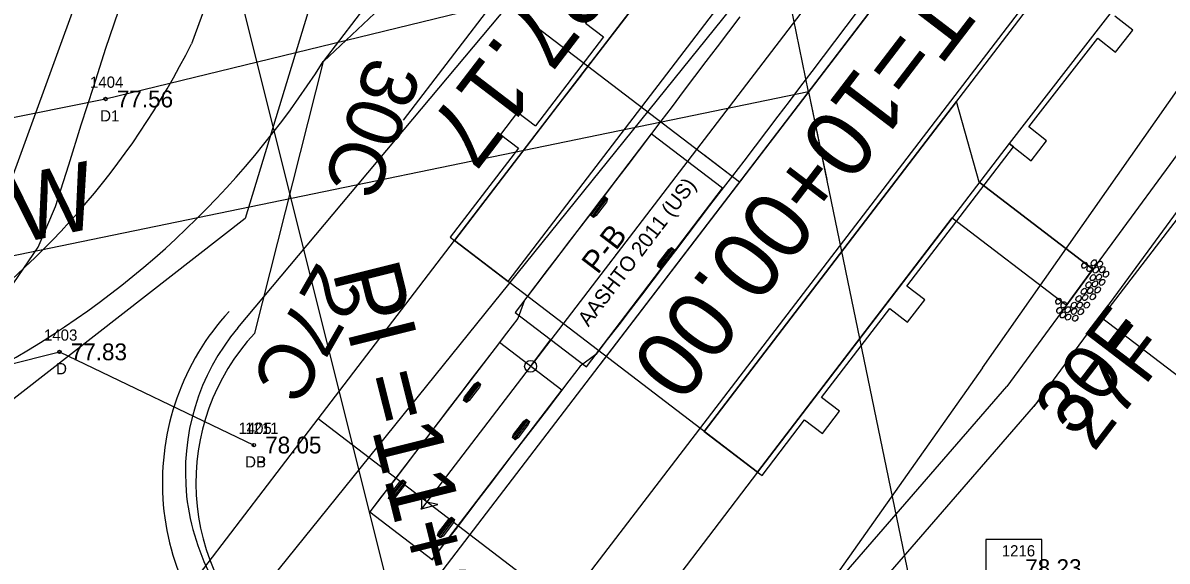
# Model space of a CAD drawing. Extents: x 2500794 to 2511032, y 910653 to 917533.
# Drawn here: x 2506102.2 to 2506204.2, y 913947.8 to 913995.8 of the extents above; entities that cross this region are included whole.
import ezdxf

# ---------------------------------------------------------------- set-up
doc = ezdxf.new("R2010")
doc.units = 0
for name, color, linetype in [('RD_EX_Driveway', 7, 'Continuous'), ('RD_EX_Driveway_txCode', 7, 'Continuous'), ('RD_EX_Road', 7, 'Continuous'), ('RD_EX_RW', 7, 'Continuous'), ('RD_EX_TX_Driveway_ELEV', 7, 'Continuous'), ('RD_EX_UT', 7, 'Continuous'), ('RD_EX_UT_txCode', 7, 'Continuous'), ('RD_HC_Cl', 7, 'Continuous'), ('RD_HC_Data', 7, 'Continuous'), ('RD_HC_Data_Rel', 7, 'Continuous'), ('RD_HC_Data_Tic', 7, 'Continuous'), ('RD_HC_Survey_ELEV', 7, 'Continuous'), ('RD_PD_ALT1_TnTmp', 7, 'Continuous'), ('RD_PD_ALT1_TrvlWay', 7, 'Continuous'), ('RD_PD_ALT2_TrvlWay', 7, 'Continuous'), ('RD_PD_Bridge', 7, 'Continuous'), ('RD_PD_CstnLmt', 7, 'Continuous'), ('RD_PD_CstnLmt_TX', 7, 'Continuous'), ('RD_PD_Detour', 7, 'Continuous'), ('RD_PD_GR', 7, 'Continuous'), ('RD_PD_PaintMed', 7, 'Continuous'), ('RD_PD_PaveShd', 7, 'Continuous'), ('RD_PD_Signals', 7, 'Continuous'), ('RD_Sketch10', 7, 'Continuous'), ('RD_SMD_Locator', 7, 'Continuous'), ('RD_XS_NPDES', 7, 'Continuous')]:
    doc.layers.add(name, color=color, linetype=linetype)

msp = doc.modelspace()

# ---------------------------------------------------------------- linework, layer by layer
at = {"layer": 'RD_EX_Driveway'}
for points in [[(2505985.77, 913963.59), (2506043.74, 913975.78), (2506109.6, 913989.05), (2506154.74, 914000.1)], [(2505819.54, 913956.76), (2505827.1, 913947.15), (2505840.35, 913935.26), (2505856.8, 913926.65), (2505912.43, 913930.56), (2505969.91, 913935.82), (2505992.8, 913939.07), (2506008.73, 913942.16), (2506105.49, 913966.5), (2506122.82, 913958.19)]]:
    msp.add_lwpolyline(points, dxfattribs=at)
at = {"layer": 'RD_EX_Road'}
for points in [[(2506114.01, 913933.8), (2506123.61, 913945.35), (2506183.7, 914019.9), (2506246.75, 914102.24), (2506309.52, 914184.62), (2506366.78, 914260.38), (2506431.55, 914345.25), (2506455.95, 914376.74), (2506469.75, 914395.23), (2506492.7, 914425.08), (2506555.84, 914508.26), (2506617.75, 914589.02), (2506679.77, 914670.81), (2506740.35, 914750.22)], [(2506132.31, 913920.14), (2506200.99, 914009.83), (2506228.78, 914046.14), (2506238.19, 914058.36), (2506261.83, 914089.97), (2506324.5, 914172.22), (2506382.84, 914247.97), (2506424.88, 914303.73), (2506446.4, 914331.89), (2506508.34, 914413.09), (2506571.21, 914495.53), (2506633.01, 914576.81), (2506694.83, 914657.95), (2506756.78, 914739.18)]]:
    msp.add_lwpolyline(points, dxfattribs=at)
at = {"layer": 'RD_EX_RW'}
for p, q in [((2506198.38, 913969.53), (2506826.41, 914790.99)), ((2506231.75, 913944.02), (2506198.38, 913969.53))]:
    msp.add_line(p, q, dxfattribs=at)
at = {"layer": 'RD_EX_UT'}
for p, q in [((2506193.06, 913949.76), (2506188.06, 913949.76)), ((2506188.06, 913949.76), (2506188.06, 913944.76)), ((2506193.06, 913944.76), (2506193.06, 913949.76))]:
    msp.add_line(p, q, dxfattribs=at)
at = {"layer": 'RD_HC_Cl'}
for p, q in [((2505807.57, 913512.69), (2506748.89, 914743.92)), ((2506172.26, 913989.7), (2505988.17, 913951.65))]:
    msp.add_line(p, q, dxfattribs=at)
at = {"layer": 'RD_HC_Data'}
for p, q in [((2506112.07, 914036.23), (2506140.23, 913923.75)), ((2506172.26, 913989.7), (2506196.98, 913870.15))]:
    msp.add_line(p, q, dxfattribs=at)
at = {"layer": 'RD_HC_Data_Rel'}
for p, q in [((2506234.44, 914115.77), (2506136.12, 913987.17)), ((2506256.03, 914099.26), (2506153.68, 913965.39))]:
    msp.add_line(p, q, dxfattribs=at)
at = {"layer": 'RD_HC_Data_Tic'}
for p, q in [((2506172.26, 913989.7), (2506170.64, 913997.54)), ((2506172.26, 913989.7), (2506173.88, 913981.87)), ((2506166.09, 913981.63), (2506162.91, 913984.06)), ((2506166.09, 913981.63), (2506162.91, 913984.06))]:
    msp.add_line(p, q, dxfattribs=at)
at = {"layer": 'RD_PD_ALT1_TnTmp'}
for p, q in [((2506206.92, 914042.96), (2506137.76, 913952.5)), ((2506100.56, 913980.07), (2506123.05, 914041.87)), ((2506158.23, 913985.93), (2506146.11, 913970.02)), ((2506164.59, 913981.09), (2506158.23, 913985.93)), ((2506152.48, 913965.17), (2506164.59, 913981.09)), ((2506152.85, 913978.66), (2506154.12, 913980.32)), ((2506152.96, 913978.58), (2506154.22, 913980.24)), ((2506153.06, 913978.5), (2506154.32, 913980.16)), ((2506158.81, 913974.13), (2506160.07, 913975.79)), ((2506158.91, 913974.05), (2506160.17, 913975.71)), ((2506159.01, 913973.97), (2506160.27, 913975.63)), ((2506146.11, 913970.02), (2506152.48, 913965.17)), ((2506144.7, 913967.34), (2506133.16, 913952.24)), ((2506150.26, 913963.08), (2506144.7, 913967.34)), ((2506147.48, 913965.21), (2506149.3, 913967.6)), ((2506152.48, 913965.17), (2506152.48, 913965.17)), ((2506141.53, 913962.15), (2506142.79, 913963.81)), ((2506141.63, 913962.07), (2506142.9, 913963.73)), ((2506141.74, 913962), (2506143, 913963.65)), ((2506138.72, 913947.99), (2506150.26, 913963.08)), ((2506145.88, 913958.83), (2506147.15, 913960.48)), ((2506145.98, 913958.75), (2506147.25, 913960.4)), ((2506146.09, 913958.67), (2506147.35, 913960.32)), ((2506134.85, 913953.42), (2506136.11, 913955.07)), ((2506134.95, 913953.34), (2506136.22, 913954.99)), ((2506135.05, 913953.26), (2506136.32, 913954.91)), ((2506133.16, 913952.24), (2506138.72, 913947.99)), ((2506139.2, 913950.09), (2506140.47, 913951.74)), ((2506139.3, 913950.01), (2506140.57, 913951.66)), ((2506139.41, 913949.93), (2506140.67, 913951.58)), ((2506138.72, 913947.99), (2506138.72, 913947.99))]:
    msp.add_line(p, q, dxfattribs=at)
for points in [[(2506101.43, 913972.67), (2506103.58, 913975.85), (2506105.13, 913979.46), (2506106.31, 913983.17), (2506107.43, 913986.74), (2506108.54, 913990.19), (2506109.63, 913993.57), (2506110.74, 913996.88)], [(2506166.12, 913996.37), (2506165.12, 913995.04), (2506164.11, 913993.71), (2506163.11, 913992.38), (2506162.1, 913991.05), (2506161.09, 913989.72), (2506160.09, 913988.39), (2506159.08, 913987.06), (2506158.07, 913985.73), (2506157.06, 913984.4), (2506156.05, 913983.07), (2506155.04, 913981.74), (2506154.03, 913980.42), (2506153.02, 913979.09), (2506152.01, 913977.76), (2506150.99, 913976.43), (2506149.98, 913975.1), (2506148.97, 913973.78), (2506147.96, 913972.45), (2506146.95, 913971.12), (2506146.34, 913969.48), (2506145.33, 913968.16), (2506144.31, 913966.83), (2506143.3, 913965.51), (2506142.28, 913964.18), (2506141.27, 913962.85), (2506140.26, 913961.53), (2506139.24, 913960.2), (2506138.23, 913958.87), (2506137.21, 913957.55), (2506136.2, 913956.22), (2506135.19, 913954.89), (2506134.17, 913953.57), (2506133.16, 913952.24)], [(2506176.58, 913996.84), (2506175.57, 913995.51), (2506174.56, 913994.17), (2506173.55, 913992.84), (2506172.54, 913991.51), (2506171.53, 913990.18), (2506170.52, 913988.84), (2506169.51, 913987.51), (2506168.5, 913986.18), (2506167.49, 913984.85), (2506166.48, 913983.52), (2506165.47, 913982.19), (2506164.45, 913980.87), (2506163.44, 913979.54), (2506162.43, 913978.21), (2506161.42, 913976.88), (2506160.4, 913975.55), (2506159.39, 913974.23), (2506158.38, 913972.9), (2506157.36, 913971.57), (2506156.35, 913970.24), (2506155.34, 913968.92), (2506154.32, 913967.59), (2506153.31, 913966.26), (2506151.9, 913965.23), (2506150.89, 913963.91), (2506149.87, 913962.58), (2506148.86, 913961.25), (2506147.85, 913959.93), (2506146.83, 913958.6), (2506145.82, 913957.28), (2506144.8, 913955.95), (2506143.79, 913954.62), (2506142.77, 913953.3), (2506141.76, 913951.97), (2506140.75, 913950.64), (2506139.73, 913949.32), (2506138.72, 913947.99)]]:
    msp.add_lwpolyline(points, dxfattribs=at)
for points in [[(2506153.09, 913978.48), (2506152.83, 913978.68), (2506152.93, 913978.97), (2506153.84, 913980.16), (2506154.09, 913980.34), (2506154.35, 913980.14), (2506154.25, 913979.85), (2506153.34, 913978.66)], [(2506159.04, 913973.95), (2506158.78, 913974.15), (2506158.88, 913974.44), (2506159.79, 913975.63), (2506160.04, 913975.81), (2506160.3, 913975.61), (2506160.2, 913975.32), (2506159.29, 913974.12)], [(2506141.76, 913961.98), (2506141.5, 913962.17), (2506141.6, 913962.46), (2506142.51, 913963.66), (2506142.77, 913963.83), (2506143.03, 913963.63), (2506142.93, 913963.34), (2506142.02, 913962.15)], [(2506146.11, 913958.65), (2506145.86, 913958.85), (2506145.95, 913959.14), (2506146.87, 913960.33), (2506147.12, 913960.5), (2506147.38, 913960.3), (2506147.28, 913960.01), (2506146.37, 913958.82)], [(2506135.08, 913953.24), (2506134.82, 913953.43), (2506134.92, 913953.73), (2506135.83, 913954.92), (2506136.09, 913955.09), (2506136.35, 913954.89), (2506136.25, 913954.6), (2506135.33, 913953.41)], [(2506137.76, 913952.5), (2506139.21, 913952.89), (2506138.22, 913953.1), (2506137.76, 913954)], [(2506139.43, 913949.91), (2506139.17, 913950.11), (2506139.27, 913950.4), (2506140.18, 913951.59), (2506140.44, 913951.76), (2506140.7, 913951.56), (2506140.6, 913951.27), (2506139.69, 913950.08)]]:
    msp.add_lwpolyline(points, close=True, dxfattribs=at)
for centre, radius in [((2506147.48, 913965.21), 0.533), ((2506137.76, 913952.5), 0.0417), ((2506133.16, 913952.24), 0.0417), ((2506138.72, 913947.99), 0.0417)]:
    msp.add_circle(centre, radius, dxfattribs=at)
at = {"layer": 'RD_PD_ALT1_TrvlWay'}
for p, q in [((2506162.95, 913959.41), (2506387.41, 914253)), ((2506145.47, 913972.77), (2506215.72, 914064.66))]:
    msp.add_line(p, q, dxfattribs=at)
at = {"layer": 'RD_PD_ALT2_TrvlWay'}
msp.add_line((2506148.92, 914080.9), (2506117.26, 913993.98), dxfattribs=at)
msp.add_arc((2506053.87, 914025.71), 70.89, 275.1042, 333.4112, dxfattribs=at)
at = {"layer": 'RD_PD_Bridge'}
for p, q in [((2506140.71, 913976.42), (2506152.85, 913992.31)), ((2506128.56, 913960.53), (2506140.71, 913976.42)), ((2506167.72, 913955.77), (2506140.71, 913976.42)), ((2506007.09, 913801.65), (2506128.56, 913960.53)), ((2506155.57, 913939.88), (2506128.56, 913960.53)), ((2506167.72, 913955.77), (2506155.57, 913939.88))]:
    msp.add_line(p, q, dxfattribs=at)
at = {"layer": 'RD_PD_CstnLmt'}
for p, q in [((2506249.07, 914044.07), (2506189.92, 913963.41)), ((2506129.01, 913992.4), (2506137.49, 914003.5)), ((2506122.89, 913968.16), (2506129.01, 913992.4)), ((2506162.89, 913932.2), (2506189.92, 913963.41))]:
    msp.add_line(p, q, dxfattribs=at)
msp.add_arc((2506137.24, 913954.83), 19.59, 137.0924, 229.3275, dxfattribs=at)
at = {"layer": 'RD_PD_Detour'}
msp.add_line((2506160.76, 914022.31), (2506129.01, 913992.4), dxfattribs=at)
msp.add_arc((2506061.16, 914035.44), 80.35, 269.2956, 327.6026, dxfattribs=at)
at = {"layer": 'RD_PD_GR'}
for p, q in [((2506227.23, 914032.89), (2506190.13, 913985.08)), ((2506140.71, 913976.42), (2506163.12, 914005.73)), ((2506153.91, 913997.8), (2506152.39, 913995.81)), ((2506201.15, 913995.2), (2506199.56, 913996.43)), ((2506152.39, 913995.81), (2506153.98, 913994.59)), ((2506199.61, 913993.23), (2506201.15, 913995.2)), ((2506153.98, 913994.59), (2506147.91, 913986.65)), ((2506191.9, 913986.56), (2506198.03, 913994.46)), ((2506198.03, 913994.46), (2506199.61, 913993.23)), ((2506146.31, 913987.87), (2506144.79, 913985.88)), ((2506146.31, 913987.87), (2506147.91, 913986.65)), ((2506193.48, 913985.33), (2506191.9, 913986.56)), ((2506144.79, 913985.88), (2506146.39, 913984.66)), ((2506190.13, 913985.08), (2506167.72, 913955.77)), ((2506190.13, 913985.08), (2506192.1, 913983.55)), ((2506190.52, 913984.78), (2506190.13, 913985.08)), ((2506192.1, 913983.55), (2506193.48, 913985.33)), ((2506146.39, 913984.66), (2506140.32, 913976.72)), ((2506181.01, 913972.35), (2506190.52, 913984.78)), ((2506140.32, 913976.72), (2506140.71, 913976.42)), ((2506182.61, 913971.13), (2506181.01, 913972.35)), ((2506181.09, 913969.15), (2506182.61, 913971.13)), ((2506173.42, 913962.42), (2506179.5, 913970.36)), ((2506179.5, 913970.36), (2506181.09, 913969.15)), ((2506175.02, 913961.2), (2506173.42, 913962.42)), ((2506173.5, 913959.21), (2506175.02, 913961.2)), ((2506168.11, 913955.47), (2506171.9, 913960.43)), ((2506171.9, 913960.43), (2506173.5, 913959.21)), ((2506167.72, 913955.77), (2506168.11, 913955.47))]:
    msp.add_line(p, q, dxfattribs=at)
at = {"layer": 'RD_PD_PaintMed'}
msp.add_line((2506166.09, 913981.63), (2506137.49, 914003.5), dxfattribs=at)
at = {"layer": 'RD_PD_PaveShd'}
for p, q in [((2506145.47, 913972.77), (2506167.97, 914002.2)), ((2506145.47, 913972.77), (2506167.97, 914002.2)), ((2506140.71, 913976.42), (2506158.04, 913999.09)), ((2506152.02, 913991.21), (2506150.28, 913988.94)), ((2506162.95, 913959.41), (2506185.45, 913988.84)), ((2506185.45, 913988.84), (2506162.95, 913959.41)), ((2506187.48, 913981.62), (2506185.45, 913988.84)), ((2506187.48, 913981.62), (2506185.45, 913988.84)), ((2506187.48, 913981.62), (2506197.6, 913973.88)), ((2506197.6, 913973.88), (2506187.48, 913981.62)), ((2506167.72, 913955.77), (2506185.05, 913978.44)), ((2506167.72, 913955.77), (2506185.05, 913978.44)), ((2506185.05, 913978.44), (2506195.24, 913970.65)), ((2506185.05, 913978.44), (2506195.24, 913970.65)), ((2506140.71, 913976.42), (2506145.47, 913972.77)), ((2506195.24, 913970.65), (2506197.6, 913973.88)), ((2506167.72, 913955.77), (2506162.95, 913959.41)), ((2506162.95, 913959.41), (2506167.72, 913955.77))]:
    msp.add_line(p, q, dxfattribs=at)
msp.add_lwpolyline([(2506158.04, 913999.09), (2506150.28, 913988.94), (2506140.71, 913976.42)], dxfattribs=at)
at = {"layer": 'RD_PD_Signals'}
for p, q in [((2506187.75, 913965.07), (2506245.23, 914047)), ((2506137.94, 914030.62), (2506122.03, 913978.4)), ((2506121.38, 913968.64), (2506145.48, 913997.39)), ((2506122.03, 913978.4), (2506088.26, 913952.05)), ((2506187.75, 913965.07), (2506166.08, 913934.35))]:
    msp.add_line(p, q, dxfattribs=at)
msp.add_arc((2506136.71, 913955.79), 20, 140.0354, 232.2705, dxfattribs=at)
at = {"layer": 'RD_Sketch10'}
for centre in [(2506197.69, 913974.45), (2506196.85, 913974.22), (2506197.31, 913973.93), (2506197.87, 913973.8), (2506198.23, 913974.33), (2506198.44, 913973.83), (2506198.77, 913973.42), (2506197.22, 913972.48), (2506197.6, 913973.12), (2506197.79, 913972.56), (2506198.14, 913973.17), (2506198.42, 913972.7), (2506196.8, 913971.9), (2506197.36, 913971.96), (2506197.6, 913971.42), (2506198.03, 913972.02), (2506194.53, 913971.01), (2506195, 913970.7), (2506195.91, 913970.66), (2506196.33, 913971.25), (2506196.43, 913970.67), (2506196.91, 913971.34), (2506197.06, 913970.67), (2506194.62, 913970.2), (2506194.93, 913969.79), (2506195.37, 913970.26), (2506195.39, 913969.6), (2506195.93, 913970.11), (2506196.03, 913969.5), (2506196.53, 913970.08)]:
    msp.add_ellipse(centre, major_axis=(0.154, 0.243), ratio=0.739412, dxfattribs=at)
at = {"layer": 'RD_SMD_Locator'}
for centre in [(2506109.6, 913989.05), (2506105.49, 913966.5), (2506122.82, 913958.19), (2506122.82, 913958.19)]:
    msp.add_circle(centre, 0.15, dxfattribs=at)
at = {"layer": 'RD_XS_NPDES'}
for p, q in [((2506251.49, 914042.29), (2506192.34, 913961.64)), ((2506192.31, 913961.59), (2506193.12, 913962.53)), ((2506165.37, 913930.51), (2506192.31, 913961.59))]:
    msp.add_line(p, q, dxfattribs=at)
msp.add_arc((2506137.26, 913954.83), 22.6, 137.4459, 229.681, dxfattribs=at)

# ---------------------------------------------------------------- texts
at = {"layer": 'RD_EX_Driveway_txCode'}
for s, p in [('1404', (2506108.21, 913990.05)), ('D1', (2506109.12, 913987.05)), ('1403', (2506104.11, 913967.5)), ('D', (2506105.19, 913964.5)), ('1405', (2506121.44, 913959.19)), ('1211', (2506122.04, 913959.19)), ('DP', (2506122.04, 913956.19)), ('DB', (2506122.04, 913956.19))]:
    msp.add_text(s, height=1, dxfattribs=at).set_placement(p)
at = {"layer": 'RD_EX_TX_Driveway_ELEV'}
for s, p in [('77.56', (2506110.6, 913988.3)), ('77.83', (2506106.49, 913965.75)), ('78.05', (2506123.82, 913957.44)), ('78.05', (2506123.82, 913957.44))]:
    msp.add_text(s, height=1.5, dxfattribs=at).set_placement(p)
at = {"layer": 'RD_EX_UT_txCode'}
msp.add_text('1216', height=1, dxfattribs=at).set_placement((2506189.48, 913948.26))
at = {"layer": 'RD_HC_Data'}
for s, rotation, p in [('S 78%%d 19\' 14" W', 11.6795, (2506054.13, 913966.3)), ('PI =11+22.08', 284.0539, (2506129.79, 913973.66))]:
    msp.add_text(s, height=6, rotation=rotation, dxfattribs=at).set_placement(p)
at = {"layer": 'RD_HC_Data_Rel'}
for s, p in [('RELOC. PC=10+27.17', (2506187.44, 914051)), ('RELOC. POT=10+00.00', (2506209.03, 914034.5))]:
    msp.add_text(s, height=6, rotation=232.6007, dxfattribs=at).set_placement(p)
at = {"layer": 'RD_HC_Survey_ELEV'}
msp.add_text('78.23', height=1.5, dxfattribs=at).set_placement((2506191.57, 913946.51))
at = {"layer": 'RD_PD_ALT1_TnTmp'}
for s, height, p in [('AASHTO 2011 (US)', 1.3333, (2506152.64, 913968.67)), ('P-B', 2, (2506153.47, 913973.34)), ('(c) 2014 Transoft Solutions, Inc. All rights reserved.', 0.08, (2506154.4, 913974.23))]:
    msp.add_text(s, height=height, rotation=52.7138, dxfattribs=at).set_placement(p)
at = {"layer": 'RD_PD_CstnLmt_TX'}
msp.add_text('30F', height=5, rotation=52.6007, dxfattribs=at).set_placement((2506196.05, 913958.73))
at = {"layer": 'RD_PD_Detour'}
msp.add_text('30C', height=5, rotation=249.9865, dxfattribs=at).set_placement((2506133.13, 913993.05))
at = {"layer": 'RD_PD_Signals'}
for s, rotation, p in [('27C', 240.2486, (2506128.54, 913974.68)), ('27F', 52.6007, (2506197.69, 913957.48))]:
    msp.add_text(s, height=5, rotation=rotation, dxfattribs=at).set_placement(p)

doc.saveas('drawing.dxf')
